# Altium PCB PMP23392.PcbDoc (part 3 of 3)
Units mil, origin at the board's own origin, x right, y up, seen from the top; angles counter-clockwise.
Board outline 5000 x 3400 mil, 6 copper layers (Top Layer, Midlayer 1, Midlayer 2, Midlayer 3, Midlayer 4, Bottom Layer), stack 61.536 mil thick; 247 components, 68 nets, 546 pads, 871 vias.
Unrouted connection lines stored in the file: 21.
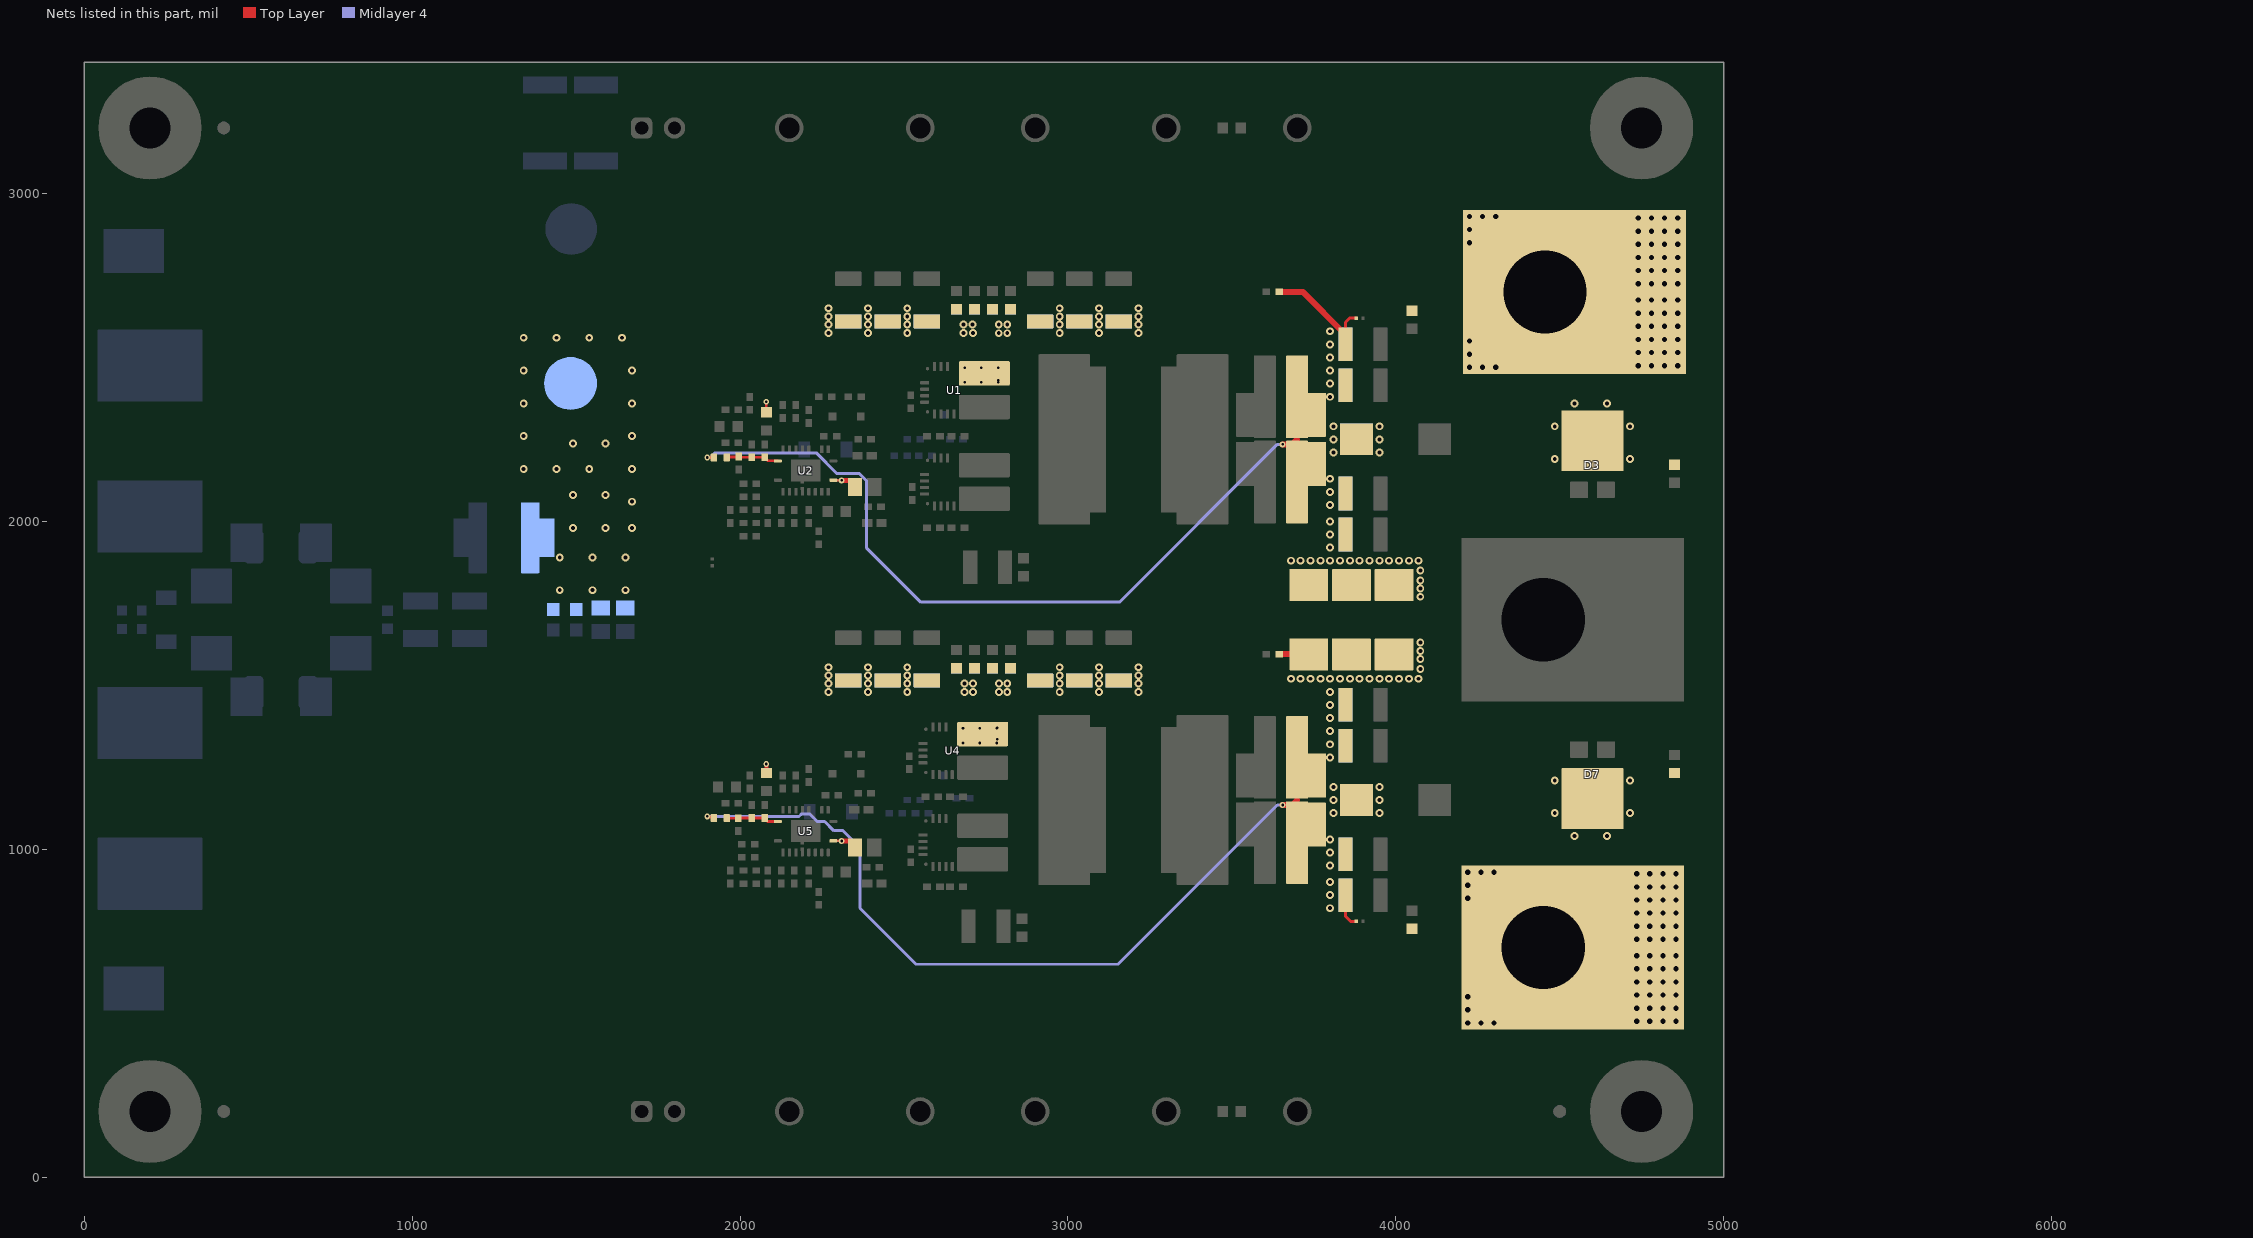
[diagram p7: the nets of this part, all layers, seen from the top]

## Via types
v1: diameter 24, hole 12, Top Layer to Bottom Layer, tented both sides, 526 vias
v2: diameter 32, hole 16, Top Layer to Bottom Layer, 174 vias
v3: diameter 18, hole 8, Top Layer to Bottom Layer, tented both sides, 77 vias
v4: diameter 24, hole 12, Top Layer to Bottom Layer, 46 vias
v5: diameter 19.68, hole 7.87, Top Layer to Bottom Layer, tented both sides, 44 vias
v6: diameter 19.68, hole 7.87, Top Layer to Bottom Layer, tented bottom, 4 vias

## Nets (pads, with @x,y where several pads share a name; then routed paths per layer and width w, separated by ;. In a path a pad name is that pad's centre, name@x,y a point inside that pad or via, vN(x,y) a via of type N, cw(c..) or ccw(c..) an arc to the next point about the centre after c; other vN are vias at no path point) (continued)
VIN: C1.2 C8.1 C9.1 C10.1 C11.1 C12.2 C13.2 C14.2 C15.2 C16.2 C17.1 C18.1 C19.1 C20.1 C21.2 C22.2 C23.2 C24.2 C25.1 C26.1 C27.1 C28.1 C29.2 C30.1 C54.2 C55.2 C56.2 C57.2 C58.2 C59.1 C60.1 C61.1 C62.1 C63.2 C64.2 C65.2 C66.2 C67.2 C68.1 C69.1 C70.1 C71.1 C72.1 C100.2 C101.2 C102.2 C103.2 J1.1 L1.1 R6.2 R29.2 U1.7 U2.10 U4.7 U5.10 | length 214.5
  Top Layer w8: R6.2@2080,2332.56 v3(2080,2365) ; U5.10@2284.65,1025.47 2284.88,1025.24 2309.76,1025.24 v3(2310,1025) ; U2.10@2284.65,2125.47 2284.88,2125.24 2309.76,2125.24 v3(2310,2125)
  Top Layer w12: R29.2@2080,1232.56 v3(2080,1260) ; C72.1@2350.47,1005 C72.1@2350.47,1009.35
  Top Layer w15: v3(2310,1025) 2334.82,1025 C72.1@2350.47,1009.35 ; v3(2310,2125) 2336.32,2125 2350.47,2110.85 C30.1@2350.47,2105
  other v1: 2270,1480 2390,1480 2510,1480 2685,1480 2710,1480 2790,1480 2815,1480 2975,1480 3095,1480 3215,1480 2270,1505 2390,1505 2510,1505 2685,1505 2710,1505 2790,1505 2815,1505 2975,1505 3095,1505 3215,1505 2270,1530 2390,1530 2510,1530 2975,1530 3095,1530 3215,1530 2270,1555 2390,1555 2510,1555 2975,1555 3095,1555 3215,1555 1450,1790 1550,1790 1650,1790 1450,1890 1550,1890 1650,1890 1490,1980 1590,1980 1670,1980 1670,2060 1490,2080 1590,2080 1340,2160 1440,2160 1540,2160 1670,2160 1490,2237.35 1590,2237.35 1340,2260 1670,2260 1340,2360 1670,2360 1340,2460 1670,2460 1340,2560 1440,2560 1540,2560 1640,2560 2789,2574 2815,2574 2270,2575 2390,2575 2510,2575 2681,2575 2710,2575 2975,2575 3095,2575 3215,2575 2270,2600 2390,2600 2510,2600 2681,2600 2709,2600 2789,2600 2815,2600 2975,2600 3095,2600 3215,2600 2270,2625 2390,2625 2510,2625 2975,2625 3095,2625 3215,2625 2270,2650 2390,2650 2510,2650 2975,2650 3095,2650 3215,2650
  other v5: 2680,1324.02 2731.18,1324.02 2782.36,1324.02 2680,1368.9 2731.18,1368.9 2782.36,1368.9 2685,2424.02 2736.18,2424.02 2787.36,2424.02 2685,2468.9 2736.18,2468.9 2787.36,2468.9
  other v6: 2785,1335 2785,1370 2788,2431 2788,2468
VOUT1: C36.1 C37.1 C38.1 C39.1 C40.1 C41.1 C42.1 C43.1 C44.1 C45.1 C46.1 C47.1 D3.3 J9.2 J10.2 J11.2 NT1.2 R5.2 R7.1 R8.2 R13.2 R64.2 R66.2 T1.1 | length 2701.6
  Top Layer w9: v3(1900,2195) R13.2@1920.32,2195 ; C38.1@3846.85,2540 3846.85,2569.53 3846.85,2607.11 3859.74,2620 NT1.2@3880,2620
  Top Layer w18: R7.1@3644.69,2700 3716.38,2700 C38.1@3846.85,2569.53 ; v3(3655,2235) 3684.21,2235 3699.21,2250
  Midlayer 4 w9: v3(1900,2195) 1910.16,2195 1924.15,2208.99 2232.37,2208.99 2294.99,2146.37 2363.78,2146.37 2385.15,2125 2385.15,1919.85 2551.45,1753.55 3157.41,1753.55 3638.86,2235 v3(3655,2235)
  other v1: 4075,1770 4075,1795 4075,1820 4075,1850 3680,1880 3710,1880 3740,1880 3770,1880 3800,1880 3830,1880 3860,1880 3890,1880 3920,1880 3950,1880 3980,1880 4010,1880 4040,1880 4070,1880 3800,1920 3800,1960 3800,2000 3800,2050 3800,2090 3800,2130 4485,2190 4715,2190 3810,2210 3950,2210 3810,2250 3950,2250 3810,2290 3950,2290 4485,2290 4715,2290 4545,2360 4645,2360 3800,2380 3800,2420 3800,2460 3800,2500 3800,2540 3800,2580
  other v2: 4225,2470 4265,2470 4305,2470 4740,2475 4780,2475 4820,2475 4860,2475 4225,2510 4740,2515 4780,2515 4820,2515 4860,2515 4225,2550 4740,2555 4780,2555 4820,2555 4860,2555 4740,2595 4780,2595 4820,2595 4860,2595 4740,2635 4780,2635 4820,2635 4860,2635 4740,2675 4780,2675 4820,2675 4860,2675 4740,2725 4780,2725 4820,2725 4860,2725 4740,2765 4780,2765 4820,2765 4860,2765 4740,2805 4780,2805 4820,2805 4860,2805 4740,2845 4780,2845 4820,2845 4860,2845 4225,2850 4740,2885 4780,2885 4820,2885 4860,2885 4225,2890 4740,2925 4780,2925 4820,2925 4860,2925 4225,2930 4265,2930 4305,2930
VOUT2: C78.1 C79.1 C80.1 C81.1 C82.1 C83.1 C84.1 C85.1 C86.1 C87.1 C88.1 C89.1 D7.3 J9.1 J10.1 J11.1 NT4.2 R30.2 R31.2 R33.2 R38.2 R65.2 R67.2 T3.1 | length 2526.5
  Top Layer w9: v3(1900,1100) 1901.72,1098.28 1917.04,1098.28 R38.2@1920.32,1095 ; J9.1@3734.19,1595 J9.1@3735,1594.19 ; C83.1@3846.85,860 3846.85,795.2 3862.05,780 NT4.2@3880,780
  Top Layer w18: R31.2@3644.69,1595 J9.1@3734.19,1595 ; v3(3655,1135) 3684.21,1135 3699.21,1150
  Midlayer 4 w9: v3(1900,1100) 1920.32,1100 1920.44,1099.88 2179.76,1099.88 2187.85,1107.96 2212.15,1107.96 2234.61,1085.5 2234.61,1084.34 2258.2,1084.34 2285.93,1056.62 2314.04,1056.62 2365.66,1005 2365.66,820.12 2536.81,648.98 3152.84,648.98 3638.86,1135 v3(3655,1135)
  other v1: 3800,820 3800,860 3800,900 3800,950 3800,990 3800,1030 4545,1040 4645,1040 3810,1110 3950,1110 4485,1110 4715,1110 3810,1150 3950,1150 3810,1190 3950,1190 4485,1210 4715,1210 3800,1280 3800,1320 3800,1360 3800,1400 3800,1440 3800,1480 3680,1520 3710,1520 3740,1520 3770,1520 3800,1520 3830,1520 3860,1520 3890,1520 3920,1520 3950,1520 3980,1520 4010,1520 4040,1520 4070,1520 4075,1550 4075,1580 4075,1605 4075,1630
  other v2: 4220,470 4260,470 4300,470 4735,475 4775,475 4815,475 4855,475 4220,510 4735,515 4775,515 4815,515 4855,515 4220,550 4735,555 4775,555 4815,555 4855,555 4735,595 4775,595 4815,595 4855,595 4735,635 4775,635 4815,635 4855,635 4735,675 4775,675 4815,675 4855,675 4735,725 4775,725 4815,725 4855,725 4735,765 4775,765 4815,765 4855,765 4735,805 4775,805 4815,805 4855,805 4735,845 4775,845 4815,845 4855,845 4220,850 4735,885 4775,885 4815,885 4855,885 4220,890 4735,925 4775,925 4815,925 4855,925 4220,930 4260,930 4300,930
VOUTsns1: C49.1 C53.2 R13.1 R16.1 U2.19 | length 158.4
  Top Layer w8: R13.1@1959.68,2195 1961.03,2196.34 1994.66,2196.34 C53.2@1996,2197.69 ; C53.2@1999.84,2195.16 2034.84,2195.16 R16.1@2035,2195.31 C49.1@2074.84,2195.31 ; C49.1@2074.84,2195.16 2074.84,2193.5 2080.84,2187.5 2082.5,2187.5 2085.47,2184.53 U2.19@2115.35,2184.53
VOUTsns2: C91.1 C95.2 R38.1 R41.1 U5.19 | length 156.9
  Top Layer w8: R38.1@1959.68,1095 1959.84,1094.84 1994.84,1094.84 C95.2@1995,1094.69 ; C95.2@1999.84,1095.16 2034.84,1095.16 R41.1@2035,1095.32 C91.1@2075,1095.32 C91.1@2075,1093.35 ; C91.1@2074.84,1093.19 C91.1@2075,1093.35 ; U5.19@2115.35,1084.53 2083.82,1084.53 C91.1@2075,1093.35
pads on no net: FID1.1 FID2.1 FID3.1 FID4.1 FID5.1 FID6.1 H1.1 H2.1 H3.1 H4.1 H5.0 H6.0 H7.0 H8.0 LBL1.0 SH-J1.0 SH-J2.0 U1.1 U1.5 U1.8 U1.9 U1.10 U1.11 U1.12 U1.13 U1.15 U3.1 U3.5 U3.10 U3.11 U3.12 U3.13 U3.15 U4.1 U4.5 U4.8 U4.9 U4.10 U4.11 U4.12 U4.13 U4.15 U6.1 U6.5 U6.10 U6.11 U6.12 U6.13 U6.15

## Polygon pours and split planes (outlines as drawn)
GND on Top Layer "TOP_LAYER_GND" (solid, remove dead copper, pour order 49): 650,1150 650,1530 745,1530 745,1655 900,1655 900,1685 1275,1685 1275,3400 5000,3400 5000,0 1325,0 1325,1150
GNDin on Top Layer "TOP_LAYER_GND_IN" (solid, remove dead copper, pour order 72): 399.45,1149.82 399.45,799.82 299.45,699.82 299.45,474.82 -0.55,474.82 -0.55,1149.82 -0.99,1149.82 -0.99,1684.82 194.01,1684.82 194.01,1655.56 454.01,1655.56 454.01,1530.56 549.01,1530.56 549.01,1149.82
+Vin_Main on Top Layer "TOP_LAYER_+Vin_Main" (solid, remove dead copper, pour order 71): 399.66,2250.58 399.66,2600.58 299.66,2700.58 299.66,2925.58 -0.34,2925.58 -0.34,1715.58 194.66,1715.58 194.66,1745.58 454.66,1745.58 454.66,1870.58 549.66,1870.58 549.66,2250.58
+Filter on Top Layer "TOP_LAYER_+Filter" (solid, remove dead copper, pour order 70): 648.74,1870.69 743.74,1870.69 743.74,1745.69 899.71,1745.69 899.71,1715.19 1234.71,1715.19 1234.71,2100.19 648.74,2100.19
VOUT2 on Top Layer "TOP_LAYER_VOUT2" (solid, remove dead copper, pour order 43): 4200,975 4475,1250 4900,1250 4900,440 3665,440 3665,1645 4090,1645 4090,1507 3885,1507 3885,1260 3915,1230 3945,1230 3975,1200 3975,1100 3945,1070 3915,1070 3885,1040 3885,775 4200,775
VIN on Top Layer "TOP_LAYER_Vin_Phase2" (solid, remove dead copper, pour order 40): 2662.3,1313.27 2662.3,1393.27 2590.56,1465 2255,1465 2255,1570 3230,1570 3230,1465 2894.03,1465 2820,1390.97 2820,1313.27
VOUT1 on Top Layer "TOP_LAYER_VOUT1" (solid, remove dead copper, pour order 38): 4192.8,2423.55 4467.8,2148.55 4900,2148.55 4900,2958.55 3665,2958.55 3665,1753.55 4090,1753.55 4090,1893 3877.8,1893 3877.8,2138.55 3907.8,2168.55 3937.8,2168.55 3967.8,2198.55 3967.8,2298.55 3937.8,2328.55 3907.8,2328.55 3877.8,2358.55 3877.8,2623.55 4192.8,2623.55
VCC2 on Top Layer "TOP_LAYER_VCC1" (solid, remove dead copper, pour order 39): 2225,1000 2235,1000 2235,970 2255,950 2285,950 2285,910 2255,910 2225,940 2225,965
VCC1 on Top Layer "TOP_LAYER_VCC1" (solid, remove dead copper, pour order 34): 2225,2100 2235,2100 2235,2070 2255,2050 2285,2050 2285,2010 2255,2010 2225,2040 2225,2065
AGND2 on Top Layer "TOP_LAYER_AGND2" (solid, remove dead copper, pour order 37): 2215,910 2150,910 2150,875 2015,875 2015,1030 1895,1030 1895,780 2215,780
AGND1 on Top Layer "TOP_LAYER_AGND1" (solid, remove dead copper, pour order 33): 2220,2010 2155,2010 2155,1975 2020,1975 2020,2130 1900,2130 1900,1880 2220,1880
SW2 on Top Layer "TOP_LAYER_SW2" (solid, remove dead copper, pour order 41): 2665,1035 2665,1285 2820,1285 2900,1365 2900,1410 3070,1410 3070,885 2900,885 2900,955 2820,1035
SW1 on Top Layer "TOP_LAYER_SW1" (solid, remove dead copper, pour order 36): 2670,2135 2670,2385 2820,2385 2900,2465 2900,2510 3070,2510 3070,1985 2900,1985 2900,2055 2820,2135
VIN on Top Layer "TOP_LAYER_Vin_Phase1" (solid, remove dead copper, pour order 35): 2665,2415 2665,2495 2600,2560 2255,2560 2255,2665 3230,2665 3230,2560 2890,2560 2825,2495 2825,2415
GND on Midlayer 2 "MIDLAYER_2_GND" (solid, remove dead copper, pour order 60): 650,1150 1325,1150 1325,0.88 4999.05,0.88 4999.05,3400.88 1275,3400.88 1275,1685 900,1685 900,1655 745,1655 745,1530 650,1530
VIN on Midlayer 2 "MIDLAYER_2_VIN" (solid, remove dead copper, pour order 32): 1535,750 1535,1505 1325,1715 1325,2840 3240,2840 3240,750
GNDin on Midlayer 2 "MIDLAYER_2_GND_IN" (solid, remove dead copper, pour order 66): 399.64,1150.3 399.64,800.3 299.64,700.3 299.64,475.3 -0.36,475.3 -0.36,1150.3 -0.8,1150.3 -0.8,1685.3 194.2,1685.3 194.2,1656.04 454.2,1656.04 454.2,1531.04 549.2,1531.04 549.2,1150.3
+Vin_Main on Midlayer 2 "MIDLAYER_2_+Vin_Main" (solid, remove dead copper, pour order 65): 399.72,2250.48 399.72,2600.48 299.72,2700.48 299.72,2925.48 -0.28,2925.48 -0.28,1715.48 194.72,1715.48 194.72,1745.48 454.72,1745.48 454.72,1870.48 549.72,1870.48 549.72,2250.48
+Filter on Midlayer 2 "MIDLAYER_2_+Filter" (solid, remove dead copper, pour order 64): 649.03,1870.5 744.03,1870.5 744.03,1745.5 900,1745.5 900,1715 1235,1715 1235,2100 649.03,2100
VOUT1 on Midlayer 2 "MIDLAYER_2_VOUT1" (solid, remove dead copper, pour order 42): 4192.5,2422.5 4467.5,2147.5 4992.5,2147.5 4992.5,2957.5 3665,2957.5 3665,1752.5 4090,1752.5 4090,1895 3877.5,1895 3877.5,2137.5 3907.5,2167.5 3937.5,2167.5 3967.5,2197.5 3967.5,2297.5 3937.5,2327.5 3907.5,2327.5 3877.5,2357.5 3877.5,2622.5 4192.5,2622.5
VOUT2 on Midlayer 2 "MIDLAYER_2_VOUT2" (solid, remove dead copper, pour order 44): 4200,975 4475,1250 5000,1250 5000,440 3665,440 3665,1645 4090,1645 4090,1505 3885,1505 3885,1260 3915,1230 3945,1230 3975,1200 3975,1100 3945,1070 3915,1070 3885,1040 3885,775 4200,775
GND on Bottom Layer "BOTTOM_LAYER_GND" (solid, remove dead copper, pour order 63): 650,1150 1325,1150 1325,0 5000,0 5000,3400 1275,3400 1275,1685 899.33,1685 899.33,1655.08 745,1655.08 745,1530.08 650,1530.08
+Filter on Bottom Layer "BOTTOM_LAYER_+Filter" (solid, remove dead copper, pour order 47): 648.28,1870.96 743.28,1870.96 743.28,1745.96 899.25,1745.96 899.25,1715 1235,1715 1235,2100.46 648.28,2100.46
VOUT2 on Bottom Layer "BOTTOM_LAYER_VOUT2" (solid, remove dead copper, pour order 57): 4200,975 4475,1250 5000,1250 5000,440 3665,440 3665,1645 4060,1645 4060,1535 3885,1535 3885,1260 3915,1230 3945,1230 3975,1200 3975,1100 3945,1070 3915,1070 3885,1040 3885,775 4200,775
VOUT1 on Bottom Layer "BOTTOM_LAYER_VOUT1" (solid, remove dead copper, pour order 56): 4192.8,2423.55 4467.8,2148.55 4992.8,2148.55 4992.8,2958.55 3665,2958.55 3665,1753.55 4057.8,1753.55 4057.8,1863.55 3877.8,1863.55 3877.8,2138.55 3907.8,2168.55 3937.8,2168.55 3967.8,2198.55 3967.8,2298.55 3937.8,2328.55 3907.8,2328.55 3877.8,2358.55 3877.8,2623.55 4192.8,2623.55
VIN on Bottom Layer "BOTTOM_LAYER_Vin_Phase1" (solid, remove dead copper, pour order 54): 2665,2415 2665,2495 2600,2560 2255,2560 2255,2665 3230,2665 3230,2560 2890,2560 2825,2495 2825,2415
VIN on Bottom Layer "BOTTOM_LAYER_Vin_Phase2" (solid, remove dead copper, pour order 55): 2662.3,1313.27 2662.3,1393.27 2590.56,1465 2255,1465 2255,1570 3230,1570 3230,1465 2894.03,1465 2820,1390.97 2820,1313.27
GNDin on Bottom Layer "BOTTOM_LAYER_GND_IN" (solid, remove dead copper, pour order 48): 400,1150 400,800 300,700 300,475 0,475 0,1150 -0.44,1150 -0.44,1685 194.56,1685 194.56,1655.74 454.56,1655.74 454.56,1530.74 549.56,1530.74 549.56,1150
+Vin_Main on Bottom Layer "BOTTOM_LAYER_+Vin_Main" (solid, remove dead copper, pour order 45): 400,2250 400,2600 300,2700 300,2925 0,2925 0,1715 195,1715 195,1745 455,1745 455,1870 550,1870 550,2250
GND on Midlayer 4 "MIDLAYER_4_GND" (solid, remove dead copper, pour order 50): 650,1150.44 1325,1150.44 1325,0.44 4999.74,0.44 4999.74,3400.44 1275,3400.44 1275,1685 899.07,1685 899.07,1655.52 745,1655.52 745,1530.52 650,1530.52
GNDin on Midlayer 4 "MIDLAYER_4_GND_IN" (solid, remove dead copper, pour order 58): 400,1150 400,800 300,700 300,475 0,475 0,1150 -0.44,1150 -0.44,1685 194.56,1685 194.56,1655.74 454.56,1655.74 454.56,1530.74 549.56,1530.74 549.56,1150
+Filter on Midlayer 4 "MIDLAYER_4_+Filter" (solid, remove dead copper, pour order 62): 648.47,1870.89 743.47,1870.89 743.47,1745.89 899.44,1745.89 899.44,1715 1235,1715 1235,2100.39 648.47,2100.39
+Vin_Main on Midlayer 4 "MIDLAYER_4_+Vin_Main" (solid, remove dead copper, pour order 51): 400,2250 400,2600 300,2700 300,2925 0,2925 0,1715 195,1715 195,1745 455,1745 455,1870 550,1870 550,2250
GND on Midlayer 3 "MIDLAYER_3_GND" (solid, remove dead copper, pour order 59): 650,1150.06 1325,1150.06 1325,0.06 4999.53,0.06 4999.53,3400.06 1275,3400.06 1275,1685 898.86,1685 898.86,1655.15 745,1655.15 745,1530.15 650,1530.15
GNDin on Midlayer 3 "MIDLAYER_3_GND_IN" (solid, remove dead copper, pour order 53): 400,1150 400,800 300,700 300,475 0,475 0,1150 -0.44,1150 -0.44,1685 194.56,1685 194.56,1655.74 454.56,1655.74 454.56,1530.74 549.56,1530.74 549.56,1150
+Filter on Midlayer 3 "MIDLAYER_3_+Filter" (solid, remove dead copper, pour order 46): 649.03,1870.5 744.03,1870.5 744.03,1745.5 900,1745.5 900,1715 1235,1715 1235,2100 649.03,2100
+Vin_Main on Midlayer 3 "MIDLAYER_3_+Vin_Main" (solid, remove dead copper, pour order 52): 400,2250 400,2600 300,2700 300,2925 0,2925 0,1715 195,1715 195,1745 455,1745 455,1870 550,1870 550,2250
GND on Midlayer 1 "MIDLAYER_1_+Filter" (solid, remove dead copper, pour order 61): 650,1150 1325,1150 1325,2.26 5000,2.26 5000,3402.26 1275,3402.26 1275,1685 900,1685 900,1655 745,1655 745,1530 650,1530
GNDin on Midlayer 1 "MIDLAYER_1_GND_IN" (solid, remove dead copper, pour order 69): 399.46,1149.97 399.46,799.97 299.46,699.97 299.46,474.97 -0.54,474.97 -0.54,1149.97 -0.99,1149.97 -0.99,1684.97 194.01,1684.97 194.01,1655.71 454.01,1655.71 454.01,1530.71 549.01,1530.71 549.01,1149.97
+Vin_Main on Midlayer 1 "MIDLAYER_1_+Vin_Main" (solid, remove dead copper, pour order 68): 399.68,2250.58 399.68,2600.58 299.68,2700.58 299.68,2925.58 -0.32,2925.58 -0.32,1715.58 194.68,1715.58 194.68,1745.58 454.68,1745.58 454.68,1870.58 549.68,1870.58 549.68,2250.58
+Filter on Midlayer 1 "MIDLAYER_1_+Filter" (solid, remove dead copper, pour order 67): 648.8,1870.66 743.8,1870.66 743.8,1745.66 899.77,1745.66 899.77,1715.16 1234.77,1715.16 1234.77,2100.16 648.8,2100.16

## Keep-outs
Keep-Out Layer:
  text ".Layer_Name" at 577,-858.49 h60

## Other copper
Top Layer:
  pour cut-out: 2391,1200 2325,1200 2325,1244 2267,1244 2245,1222 2245,1115 2215,1115 2229.84,1129.84 2229.84,1240.84 2262,1273 2391,1273
  pour cut-out: 2259,2332 2317,2332 2317,2280 2391,2280 2391,2360 2269,2360 2250,2341 2226,2341 2226,2226 2215,2215 2245,2215 2245,2271 2259,2285
  pour cut-out: 2255,2663 3230,2663 3230,2687 2255,2687
  pour cut-out: 2255,1568 3230,1568 3230,1592 2255,1592
  pour cut-out: 3635,1420 3665,1420 3665,880 3635,880
  pour cut-out: 3635,2520 3665,2520 3665,1980 3635,1980
  pour cut-out: 2920,1415 2920,1460 3480,1460 3480,1415 3305,1415 3305,885 3480,885 3480,840 2920,840 2920,880 3095,880 3095,1415
  pour cut-out: 2920,2515 2920,2560 3480,2560 3480,2515 3305,2515 3305,1985 3480,1985 3480,1940 2920,1940 2920,1980 3095,1980 3095,2515
  region net NetL4_2: 3635,1990 3330,1990 3330,2510 3635,2510
  region net NetL6_2: 3635,890 3330,890 3330,1410 3635,1410
  text ".Layer_Name" at 577,-858.49 h60
Bottom Layer:
  rectangle net NetC1_1: 1325,2765 1645,3130
  pour cut-out: 1315,1715 1315,1685 1710,1685 1710,1715 1540,1715
  pour cut-out: 2255,1568 3230,1568 3230,1592 2255,1592
  pour cut-out: 2255,2663 3230,2663 3230,2687 2255,2687
  pour cut-out: 1645,3010 1830,3010 1830,2305 1690,2305 1690,2575 1305,2575 1305,2765 1645,2765
  region net VIN: 1325,1715 1325,2575 1690,2575 1690,1715
  text ".Layer_Name" at 577,-858.49 h60

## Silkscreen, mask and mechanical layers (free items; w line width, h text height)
Top Overlay:
  lines w5.91: 2927.28,2525.28 2927.28,2549.21 ; 2932.28,1425.28 2932.28,1449.21 ; 3468,1425 3468,1448.93 ; 3468,2525 3468,2548.93
  lines w6: 1938,1086 1942,1086 ; 1938,1104 1942,1104 ; 1938,2186 1942,2186 ; 1938,2204 1942,2204 ; 1961,913 1961,917 ; 1961,2013 1961,2017 ; 1973,1131 1977,1131 ; 1973,1149 1977,1149 ; 1973,2231 1977,2231 ; 1973,2249 1977,2249 ; 1973,2331 1977,2331 ; 1973,2349 1977,2349 ; 1979,913 1979,917 ; 1979,2013 1979,2017 ; 1986,1073 1986,1077 ; 1987,2176 1987,2180 ; 2004,1073 2004,1077 ; 2005,2176 2005,2180 ; 2021,1203 2021,1207 ; 2021,2358 2021,2362 ; 2023,966 2027,966 ; 2023,984 2027,984 ; 2023,1006 2027,1006 ; 2023,1024 2027,1024 ; 2026,1113 2026,1117 ; 2026,2213 2026,2217 ; 2028,886 2032,886 ; 2028,904 2032,904 ; 2028,926 2032,926 ; 2028,944 2032,944 ; 2028,1946 2032,1946 ; 2028,1964 2032,1964 ; 2028,1986 2032,1986 ; 2028,2004 2032,2004 ; 2028,2026 2032,2026 ; 2028,2044 2032,2044 ; 2028,2066 2032,2066 ; 2028,2084 2032,2084 ; 2028,2106 2032,2106 ; 2028,2124 2032,2124 ; 2039,1203 2039,1207 ; 2039,2358 2039,2362 ; 2044,1113 2044,1117 ; 2044,2213 2044,2217 ; 2066,1113 2066,1117 ; 2066,2213 2066,2217 ; 2076,913 2076,917 ; 2076,2013 2076,2017 ; 2084,1113 2084,1117 ; 2084,2213 2084,2217 ; 2094,913 2094,917 ; 2094,2013 2094,2017 ; 2116,913 2116,917 ; 2116,2013 2116,2017 ; 2121,1203 2121,1207 ; 2121,2333 2121,2337 ; 2134,913 2134,917 ; 2134,2013 2134,2017 ; 2139,1203 2139,1207 ; 2139,2333 2139,2337 ; 2156,913 2156,917 ; 2156,2013 2156,2017 ; 2161,1203 2161,1207 ; 2161,2333 2161,2337 ; 2174,913 2174,917 ; 2174,2013 2174,2017 ; 2179,1203 2179,1207 ; 2179,2333 2179,2337 ; 2201,913 2201,917 ; 2201,1223 2201,1227 ; 2201,2013 2201,2017 ; 2201,2318 2201,2322 ; 2219,913 2219,917 ; 2219,1223 2219,1227 ; 2219,2013 2219,2017 ; 2219,2318 2219,2322 ; 2231,848 2231,852 ; 2231,1948 2231,1952 ; 2249,848 2249,852 ; 2249,1948 2249,1952 ; 2258,2371 2262,2371 ; 2258,2389 2262,2389 ; 2273,2251 2277,2251 ; 2273,2269 2277,2269 ; 2278,1156 2282,1156 ; 2278,1174 2282,1174 ; 2348,1281 2352,1281 ; 2348,1299 2352,1299 ; 2348,2371 2352,2371 ; 2348,2389 2352,2389 ; 2378,1161 2382,1161 ; 2378,1179 2382,1179 ; 2378,2241 2382,2241 ; 2378,2259 2382,2259 ; 2403,936 2407,936 ; 2403,954 2407,954 ; 2408,2036 2412,2036 ; 2408,2054 2412,2054 ; 2506,1263 2506,1267 ; 2511,978 2511,982 ; 2511,2363 2511,2367 ; 2516,2083 2516,2087 ; 2524,1263 2524,1267 ; 2529,978 2529,982 ; 2529,2363 2529,2367 ; 2534,2083 2534,2087 ; 2583,1151 2587,1151 ; 2583,1169 2587,1169 ; 2588,876 2592,876 ; 2588,894 2592,894 ; 2588,1971 2592,1971 ; 2588,1989 2592,1989 ; 2588,2251 2592,2251 ; 2588,2269 2592,2269 ; 2658,876 2662,876 ; 2658,894 2662,894 ; 2658,1151 2662,1151 ; 2658,1169 2662,1169 ; 2663,1971 2667,1971 ; 2663,1989 2667,1989 ; 2663,2251 2667,2251 ; 2663,2269 2667,2269
  text "'.PRJ_Number'.PCB_Rev" at 675,330 h108.27
  text ".Layer_Name" at 577,-858.49 h60
Bottom Overlay:
  circle w20: c400,1485 r10
  lines w6: 1147.91,2020.09 1147.91,2086.02 ; 1412.09,2020.09 1412.09,2086.02
  text ".Layer_Name" at 577,-858.49 h60
Top Paste:
  text ".Layer_Name" at 577,-858.49 h60
Bottom Paste:
  text ".Layer_Name" at 577,-858.49 h60
Top Solder:
  region: 3790,1406 3666,1406 3666,894 3790,894
  rectangle: 3509.9,894 3634,1406
  rectangle: 3510,1994 3634,2506
  region: 3789.91,2506 3666,2506 3666,1994 3789.91,1994
  text ".Layer_Name" at 577,-858.49 h60
  text ".Layer_Name" at 577,-858.49 h60
Bottom Solder:
  text ".Layer_Name" at 577,-858.49 h60
Drill Guide:
  text ".Layer_Name" at 577,-858.49 h60
M1 Board Outline:
  the board outline again, w10
  text ".Layer_Name" at 577,-858.49 h60
M2 Board Dimensions:
  rectangle: 125,-400 500,-275
  rectangle: 0,-275 125,-150
  lines w7: 0,-275 1000,-275 ; 125,-400 125,-150 ; 250,-400 250,-150 ; 500,-400 500,-150 ; 750,-400 750,-150 ; 0,-400 0,-150 1000,-150 1000,-400 0,-400
  text ".Layer_Name" at 577,-858.49 h60
M3 3D STEP Top:
  text ".Layer_Name" at 577,-858.49 h60
M4 3D STEP Bottom:
  text ".Layer_Name" at 577,-858.49 h60
M5 Assembly Top:
  lines w10: -292,-930.17 6308,-930.17 ; -292,-726.83 6310,-726.83 ; -292,-523.5 -292,-1133.5 3713,-1133.5 6310,-1133.5 6310,-523.5 -291.5,-523.5 -291.5,-1133.5 1284,-1133.5 ; 2173,-1133.5 2173,-523.5 ; 3440,-726.83 3440,-523.5 ; 4280,-726.83 4280,-523.5 ; 4902,-1140 4902,-937.17
  text "COMPONENTS MARKED 'DNP' SHOULD NOT BE POPULATED." at 1153.5,-318.5 h60
  text "ASSEMBLY VARIANT:" at 1153,-434 h60
  text ".VariantName" at 2189,-434 h60
  text "PCB VIEWED FROM TOP SIDE" at -228.5,-655.67 h60
  text "BOARD #:" at 2248,-655.67 h60
  text ".PRJ_Number" at 2793.5,-655.67 h60
  text "REV:" at 3638,-655.67 h60
  text ".PCB_Rev" at 3929.5,-655.67 h60
  text "SVN REV:" at 4476,-655.67 h60
  text ".VersionControl_RevNumber" at 4982,-655.67 h60
  text "PLOT NAME =" at -228.5,-1064.34 h60
  text ".plot_File_Name" at 577,-1064.34 h60
  text "GENERATED    :" at 2250,-1064.34 h60
  text ".Print_Date" at 3119.5,-1064.34 h60
  text ".Print_Time" at 3848.5,-1064.34 h60
  text "TEXAS INSTRUMENTS" at 5113,-1064.34 h60
M6 Assembly Bottom:
  lines w10: -292.5,-727.33 6309.5,-727.33 ; -290.5,-930.67 6309.5,-930.67 ; 1115.5,-1140.5 1115.5,-937.67 ; 1737.5,-727.33 1737.5,-524 ; 2577.5,-727.33 2577.5,-524 ; 3844.5,-1134 3844.5,-524 ; 4733.5,-1134 6309,-1134 6309,-524 -292.5,-524 -292.5,-1134 2304.5,-1134 6309.5,-1134 6309.5,-524
  text "COMPONENTS MARKED 'DNP' SHOULD NOT BE POPULATED." at 6102,-318 h60
  text ".VariantName" at 5058,-434 h60
  text "ASSEMBLY VARIANT:" at 6097,-434 h60
  text ".VersionControl_RevNumber" at 1035.5,-656.17 h60
  text "SVN REV:" at 1541.5,-656.17 h60
  text ".PCB_Rev" at 2088,-656.17 h60
  text "REV:" at 2379.5,-656.17 h60
  text ".PRJ_Number" at 3224,-656.17 h60
  text "BOARD #:" at 3769.5,-656.17 h60
  text "PCB VIEWED FROM BOTTOM SIDE" at 6246,-656.17 h60
  text "TEXAS INSTRUMENTS" at 904.5,-1064.84 h60
  text ".Print_Time" at 2169,-1064.84 h60
  text ".Print_Date" at 2898,-1064.84 h60
  text "GENERATED    :" at 3767.5,-1064.84 h60
  text ".plot_File_Name" at 5440.5,-1064.84 h60
  text "PLOT NAME =" at 6246,-1064.84 h60
M9 Title Sheet:
  drawing of 56 lines, arcs and shapes, not listed
  text "1" at 1058.34,13381.39 h70
  text "2" at 4384,13381.39 h70
  text "3" at 7714,13381.39 h70
  text "4" at 11049,13381.39 h70
  text "5" at 14374,13381.39 h70
  text "6" at 17709,13381.39 h70
  text "A" at -463,11603.39 h70
  text "A" at 19237,11603.39 h70
  text "B" at -463,7853.39 h70
  text "B" at 19237,7853.39 h70
  text "C" at -463,4103.39 h70
  text "C" at 19237,4103.39 h70
  text "D" at -463,353.39 h70
  text "D" at 19237,353.39 h70
  text "PROJECT TITLE:" at 16143,268.39 h45
  text ".PRJ_Title" at 16193,135.06 h70
  text "DESIGNED FOR:" at 16143,-32.61 h45
  text ".PRJ_Customer" at 16193,-172.61 h70
  text "FILE NAME:" at 16143,-332.61 h45
  text ".PCB_File_Name_No_Path" at 16193,-452.61 h70
  text "Texas Instruments (TI) and/or its licensors do not warrant the accuracy or completeness of this specification" at 11173.5,-614.45 h45
  text "ENGINEER:" at 16143,-622.61 h45
  text "LAYOUT BY:" at 17648,-622.61 h45
  text "or any information contained therein. TI and/or its licensors do not warrant that this design will meet" at 11128.51,-727.11 h45
  text ".PRJ_Engineer" at 16193,-777.6 h70
  text ".PCB_Layout" at 17698.5,-777.6 h70
  text "the specifications, will be suitable for your application or fit for any particular purpose, or will operate in" at 11128.51,-839.78 h45
  text ".Layer_Name" at 577,-858.49 h60
  text "ALTIUM DESIGNER VERSION:" at 17648,-932.61 h45
  text "an implementation. TI and/or its licensors do not warrant that the design is production worthy. You should" at 11128.51,-952.44 h45
  text "completely validate and test your design implementation to confirm the system functionality for your application." at 11173.5,-1065.11 h45
  text ".print_Scale" at 16193,-1065.94 h70
  text ".Application_BuildNumber" at 17698.5,-1065.94 h70
  text "1" at 1058.34,-1318.61 h70
  text "2" at 4384,-1318.61 h70
  text "3" at 7714,-1318.61 h70
  text "4" at 11049,-1318.61 h70
  text "5" at 14374,-1318.61 h70
  text "6" at 17709,-1318.61 h70
M10 Fab Notes:
  drawing of 189 lines, arcs and shapes, not listed
  text "DESIGN INFORMATION" at 17178.02,6365.17 h60
  text "MIN. TRACK WIDTH:" at 16533.46,6233.05 h60
  text "6" at 17629.7,6233.05 h60
  text "MIL" at 17784.46,6233.05 h60
  text "MIN. CLEARANCE:" at 16533.46,6108.92 h60
  text "MIL" at 17784.46,6108.92 h60
  text "7.874" at 17459.65,6104.33 h60
  text "MIN. VIA PAD SIZE:" at 16533.46,5984.8 h60
  text "18" at 17599.71,5984.8 h60
  text "MIL" at 17784.46,5984.8 h60
  text "0.127mm (5MIL)" at 17228.46,5854.9 h60
  text "MINIMUM ANNULAR RING" at 16204.23,5846.67 h60
  text "EXTERNAL" at 17936.46,5846.67 h60
  text "PER" at 16404.23,5736.55 h60
  text "IPC-D-275 CLASS 2 LEVEL C" at 16624.23,5736.54 h60
  text "MIL, HOLES" at 18112.46,5636.07 h60
  text "+/-" at 17720,5627.48 h60
  text "+/-" at 18574,5627.48 h60
  text "REGISTRATION TOLERANCES:" at 16204.23,5626.42 h60
  text "METAL" at 17404,5626.42 h60
  text "5" at 17980.2,5626.42 h60
  text "3" at 18813.2,5626.42 h60
  text "MIL" at 18929.46,5626.42 h60
  text "HOLE SIZE TOLERANCE (UNLESS OTHERWISE SPECIFIED):" at 16204.23,5528.1 h60
  text "+/-" at 18574,5525.23 h60
  text "3" at 18813.2,5524.17 h60
  text "MIL" at 18929.46,5524.17 h60
  text "MATERIAL:" at 16129.46,5386.52 h60
  text "FR-4 High Tg" at 17115.9,5258 h60
  text "X" at 16971.46,5250.01 h60
  text "FR-4" at 16550.46,5245.49 h60
  text "OTHER" at 18038.46,5245.49 h60
  text "62 MIL (1.6mm) +/-10%" at 16870.56,5102.46 h60
  text "X" at 16750.46,5100.01 h60
  text "THICKNESS:" at 16204.23,5094.24 h60
  text "OTHER" at 18155.46,5094.24 h60
  text "TOLERANCE:" at 16204.23,4955.92 h60
  text "X" at 17052.46,4955.92 h60
  text "ANSI IPC-6012 TYPE 3 CLASS 2" at 17230.48,4955.92 h60
  text "OTHER +/-" at 17230.46,4811.73 h60
  text "BOW & TWIST:" at 16204.23,4666.54 h60
  text "X" at 17052.46,4666.54 h60
  text "ANSI IPC-6012 TYPE 3 CLASS 2" at 17230.48,4666.54 h60
  text "OTHER +/-" at 17230.46,4519.85 h60
  text "DRILLING:" at 16129.46,4389.23 h60
  text "NC_DRILL FILES" at 17890.46,4284.04 h60
  text "REFERENCE:" at 16204.23,4280.1 h60
  text "X" at 16861.46,4280.01 h60
  text "AS SHOWN" at 17039.46,4280.1 h60
  text "X" at 17762.46,4280.1 h60
  text "OTHER" at 18188.46,4137.85 h60
  text "PTH COPPER THICKNESS:" at 16203.91,4134.32 h60
  text "X" at 17343.14,4134.32 h60
  text "20-30 um" at 17471.14,4134.32 h60
  text "BOARD FINISH:" at 16129.46,3986.73 h60
  text "SILKSCREEN:" at 16284.68,3876.6 h60
  text "X" at 17242.46,3876.6 h60
  text "TOP" at 17359.46,3876.6 h60
  text "X" at 17752.46,3876.6 h60
  text "BOTTOM" at 17870.46,3876.6 h60
  text "SILKSCREEN COLOR:" at 16284.68,3721.41 h60
  text "X" at 17241.46,3721.41 h60
  text "WHITE" at 17359.46,3721.41 h60
  text "OTHER" at 17870.46,3721.41 h60
  text "X" at 17372.46,3577.96 h60
  text "GREEN" at 17490.46,3577.96 h60
  text "OTHER" at 18108.46,3577.96 h60
  text "SOLDER RESIST COLOR:" at 16284.68,3571.1 h60
  text "X" at 17372.46,3423.71 h60
  text "MATTE" at 17490.46,3423.71 h60
  text "SEMI-GLOSS" at 18108,3423.07 h60
  text "IMMERSION GOLD (ENIG)" at 17190.46,3250.94 h60
  text "ENEPIG" at 18528,3243.72 h60
  text "SURFACE FINISH:" at 16129.46,3242.72 h60
  text "X" at 17012.46,3242.72 h60
  text "IMM. TIN/SILVER OR EQUIV" at 16459,3105.4 h60
  text "OTHER" at 17890.46,3101.47 h60
  text "ARRAY/PANEL:" at 16129.46,2946.09 h60
  text "X" at 17012.46,2937.87 h60
  text "CUT AND TRIM PER M1 BOARD OUTLINE" at 17190.46,2937.87 h60
  text "N.C. ROUTE" at 17190.46,2801.9 h60
  text "V. SCORE" at 18056.46,2801.9 h60
  text "CERTIFICATION:" at 16129.46,2672.77 h60
  text "MATERIALS AND WORKMANSHIP FOR ALL PCBS" at 16854.46,2672.77 h60
  text "TO MEET OR EXCEED THE REQUIREMENTS OF:" at 16854.46,2578.71 h60
  text "X" at 16491.97,2450.08 h60
  text "ANSI IPC-A-600F CLASS ->" at 16619.96,2450.08 h60
  text "X" at 18267.97,2450.08 h60
  text "2" at 18377.96,2450.08 h60
  text "1" at 18062.96,2448.58 h60
  text "3" at 18731.96,2448.58 h60
  text "X" at 17303.97,2302.39 h60
  text "RoHS" at 17431.96,2302.39 h60
  text "OTHER" at 18076.36,2302.39 h60
  text "PER ORDER" at 18473.42,2302.39 h60
  text "ALL BOARDS MUST MEET OR EXCEED UL94-V0 REQUIREMENTS." at 16157,2148.57 h60
  text "PCB MUST BEAR THE UL94V-0 UL REGISTERED MATERIAL ID NUMBER" at 16157,2032.5 h60
  text "ADDITIONAL REQUIREMENTS:" at 16129.46,1863.08 h60
  text "MICROSECTION:" at 16204.23,1755.95 h60
  text "YES" at 17109.96,1755.95 h60
  text "REQUIRED" at 17971.46,1611.62 h60
  text "BARE BOARD ELEC. TEST:" at 16204.23,1608.76 h60
  text "NONE" at 17509.96,1608.76 h60
  text "X" at 17853.46,1608.76 h60
  text "PER ORDER" at 18563.46,1608.76 h60
  text "XX MIL VIAS REQUIRE NON-CONDUCTIVE FILL AND PLANARIZE" at 16372.38,1403.82 h59
  text "XX MIL VIAS REQUIRE CONDUCTIVE FILL AND PLANARIZE" at 16380.38,1299.84 h60
  text "OUTER XX MIL TRACES REQUIRE 50 OHM SINGLE-ENDED IMPEDANCE" at 16379.39,1136.46 h58
  text "LAYER 2 & 3 (INNER LAYERS) XX MIL WIDE, XX MIL SPACE / TRACES REQUIRE 100 OHM DIFFERENTIAL IMPEDANCE" at 16371.39,900.74 h60
  text ".Layer_Name" at 577,-858.49 h60
M11 Gerber Information:
  lines w10: -292,-930.17 6308,-930.17 ; -292,-726.83 6310,-726.83 ; -292,-523.5 -292,-1133.5 3713,-1133.5 6310,-1133.5 6310,-523.5 -291.5,-523.5 -291.5,-1133.5 1284,-1133.5 ; 2173,-1133.5 2173,-523.5 ; 3440,-726.83 3440,-523.5 ; 4280,-726.83 4280,-523.5 ; 4902,-1140 4902,-937.17
  text "ALL ARTWORK VIEWED FROM TOP SIDE" at -228.5,-655.67 h60
  text "BOARD #:" at 2248,-655.67 h60
  text ".PRJ_Number" at 2793.5,-655.67 h60
  text "REV:" at 3638,-655.67 h60
  text ".PCB_Rev" at 3929.5,-655.67 h60
  text "SVN REV:" at 4476,-655.67 h60
  text ".VersionControl_RevNumber" at 4982,-655.67 h60
  text "LAYER NAME =" at -228.5,-858.49 h60
  text "PLOT NAME =" at -228.5,-1064.34 h60
  text ".plot_File_Name" at 577,-1064.34 h60
  text "GENERATED    :" at 2250,-1064.34 h60
  text ".Print_Date" at 3119.5,-1064.34 h60
  text ".Print_Time" at 3848.5,-1064.34 h60
  text "TEXAS INSTRUMENTS" at 5113,-1064.34 h60
M12 Stackup:
  drawing of 399 lines, arcs and shapes, not listed
  text "Layer" at 14605.06,13091.48 h60
  text "Name" at 15014.97,13091.48 h60
  text "Material" at 15944.72,13091.48 h60
  text "Thickness" at 16804.48,13091.48 h60
  text "Constant" at 17454.32,13091.48 h60
  text "Board Layer Stack" at 18024.18,13091.48 h60
  text "Top Overlay" at 15014.97,12971.48 h60
  text "Top Solder" at 15014.97,12851.48 h60
  text "Solder Resist" at 15944.72,12851.48 h60
  text "0.40mil" at 16804.48,12851.48 h60
  text "3.5" at 17454.32,12851.48 h60
  text "1" at 14605.06,12731.48 h60
  text "Top Layer" at 15014.97,12731.48 h60
  text "CF-005" at 15944.72,12731.48 h60
  text "2.76mil" at 16804.48,12731.48 h60
  text "Dielectric 1" at 15014.97,12611.48 h60
  text "PP-023" at 15944.72,12611.48 h60
  text "9.00mil" at 16804.48,12611.48 h60
  text "4.5" at 17454.32,12611.48 h60
  text "2" at 14605.06,12491.48 h60
  text "Midlayer 1" at 15014.97,12491.48 h60
  text "CF-004" at 15944.72,12491.48 h60
  text "2.76mil" at 16804.48,12491.48 h60
  text "Dielectric 2" at 15014.97,12371.48 h60
  text "PP-023" at 15944.72,12371.48 h60
  text "9.00mil" at 16804.48,12371.48 h60
  text "4.5" at 17454.32,12371.48 h60
  text "3" at 14605.06,12251.48 h60
  text "Midlayer 2" at 15014.97,12251.48 h60
  text "CF-004" at 15944.72,12251.48 h60
  text "2.76mil" at 16804.48,12251.48 h60
  text "Dielectric3" at 15014.97,12131.48 h60
  text "Core-034" at 15944.72,12131.48 h60
  text "9.00mil" at 16804.48,12131.48 h60
  text "4.6" at 17454.32,12131.48 h60
  text "4" at 14605.06,12011.48 h60
  text "Midlayer 3" at 15014.97,12011.48 h60
  text "CF-004" at 15944.72,12011.48 h60
  text "2.76mil" at 16804.48,12011.48 h60
  text "Dielectric 4" at 15014.97,11891.48 h60
  text "PP-023" at 15944.72,11891.48 h60
  text "9.00mil" at 16804.48,11891.48 h60
  text "4.5" at 17454.32,11891.48 h60
  text "5" at 14605.06,11771.48 h60
  text "Midlayer 4" at 15014.97,11771.48 h60
  text "CF-004" at 15944.72,11771.48 h60
  text "2.76mil" at 16804.48,11771.48 h60
  text "Dielectric 5" at 15014.97,11651.48 h60
  text "PP-023" at 15944.72,11651.48 h60
  text "9.00mil" at 16804.48,11651.48 h60
  text "4.5" at 17454.32,11651.48 h60
  text "6" at 14605.06,11531.48 h60
  text "Bottom Layer" at 15014.97,11531.48 h60
  text "CF-005" at 15944.72,11531.48 h60
  text "2.76mil" at 16804.48,11531.48 h60
  text "Bottom Solder" at 15014.97,11411.48 h60
  text "Solder Resist" at 15944.72,11411.48 h60
  text "0.40mil" at 16804.48,11411.48 h60
  text "3.5" at 17454.32,11411.48 h60
  text "Bottom Overlay" at 15014.97,11291.48 h60
  text ".Layer_Name" at 577,-858.49 h60
M13 Component Bodies Top:
  text ".Layer_Name" at 577,-858.49 h60
M14 Component Bodies Bottom:
  text ".Layer_Name" at 577,-858.49 h60
M15 Courtyards Top:
  text ".Layer_Name" at 577,-858.49 h60
M16 Courtyards Bottom:
  text ".Layer_Name" at 577,-858.49 h60
Drill Drawing:
  circle w10: c8443.72,2538.36 r27.63
  lines w10: 8416.09,2400.23 8429.9,2400.23 8429.9,2386.42 8457.53,2386.42 8457.53,2400.23 8471.34,2400.23 8471.34,2427.86 8457.53,2427.86 8457.53,2441.67 8429.9,2441.67 8429.9,2427.86 8416.09,2427.86 8416.09,2400.23 ; 8416.09,2635.06 8443.72,2648.87 8471.34,2635.06 8457.53,2662.68 8471.34,2690.31 8443.72,2676.5 8416.09,2690.31 8429.9,2662.68 8416.09,2635.06 ; 8416.09,2814.63 8471.34,2814.63 8443.72,2759.38 8416.09,2814.63 ; 8416.09,2883.7 8416.09,2897.51 8429.9,2911.32 8416.09,2925.14 8416.09,2938.95 8429.9,2938.95 8443.72,2925.14 8457.53,2938.95 8471.34,2938.95 8471.34,2925.14 8457.53,2911.32 8471.34,2897.51 8471.34,2883.7 8457.53,2883.7 8443.72,2897.51 8429.9,2883.7 8416.09,2883.7 ; 8416.09,3008.02 8471.34,3008.02 8471.34,3063.27 8416.09,3063.27 8416.09,3008.02 ; 8416.09,3159.96 8443.72,3132.34 8471.34,3159.96 8443.72,3187.59 8416.09,3159.96 ; 8416.09,3270.47 8429.9,3270.47 8443.72,3256.66 8457.53,3270.47 8471.34,3270.47 8457.53,3284.28 8471.34,3298.1 8457.53,3298.1 8443.72,3311.91 8429.9,3298.1 8416.09,3298.1 8429.9,3284.28 8416.09,3270.47
  lines w12: 8366,2349.12 11597.49,2349.12 ; 8366,3343.68 11597.49,3343.68 ; 8703.86,2224.8 8703.86,3468 ; 9035.86,2224.8 9035.86,3468 ; 9672.43,2224.8 9672.43,3468 ; 9931.57,2224.8 9931.57,3468 ; 10306.72,2224.8 10306.72,3468 ; 11031.05,2224.8 11031.05,3468 ; 8366,2224.8 11597.49,2224.8 11597.49,3468 8366,3468 8366,2224.8
  text "Symbol" at 8440.59,3380.98 h72
  text "Quantity" at 8741.16,3380.98 h72
  text "Finished Hole Size" at 9073.16,3380.98 h72
  text "Plated" at 9709.72,3380.98 h72
  text "Hole Type" at 9968.86,3380.98 h72
  text "Drill Layer Pair" at 10344.02,3380.98 h72
  text "Hole Tolerance" at 11068.35,3380.98 h72
  text "48" at 8741.16,3256.66 h60
  text "7.87mil (0.200mm)" at 9073.16,3256.66 h60
  text "PTH" at 9709.72,3256.66 h60
  text "Round" at 9968.86,3256.66 h60
  text "Top Layer - Bottom Layer" at 10344.02,3256.66 h60
  text "77" at 8741.16,3132.34 h60
  text "8.00mil (0.203mm)" at 9073.16,3132.34 h60
  text "PTH" at 9709.72,3132.34 h60
  text "Round" at 9968.86,3132.34 h60
  text "Top Layer - Bottom Layer" at 10344.02,3132.34 h60
  text "572" at 8741.16,3008.02 h60
  text "12.00mil (0.305mm)" at 9073.16,3008.02 h60
  text "PTH" at 9709.72,3008.02 h60
  text "Round" at 9968.86,3008.02 h60
  text "Top Layer - Bottom Layer" at 10344.02,3008.02 h60
  text "174" at 8741.16,2883.7 h60
  text "16.00mil (0.406mm)" at 9073.16,2883.7 h60
  text "PTH" at 9709.72,2883.7 h60
  text "Round" at 9968.86,2883.7 h60
  text "Top Layer - Bottom Layer" at 10344.02,2883.7 h60
  text "4" at 8741.16,2759.38 h60
  text "40.00mil (1.016mm)" at 9073.16,2759.38 h60
  text "PTH" at 9709.72,2759.38 h60
  text "Round" at 9968.86,2759.38 h60
  text "Top Layer - Bottom Layer" at 10344.02,2759.38 h60
  text "10" at 8741.16,2635.06 h60
  text "63.00mil (1.600mm)" at 9073.16,2635.06 h60
  text "PTH" at 9709.72,2635.06 h60
  text "Round" at 9968.86,2635.06 h60
  text "Top Layer - Bottom Layer" at 10344.02,2635.06 h60
  text "4" at 8741.16,2510.74 h60
  text "125.98mil (3.200mm)" at 9073.16,2510.74 h60
  text "PTH" at 9709.72,2510.74 h60
  text "Round" at 9968.86,2510.74 h60
  text "Top Layer - Bottom Layer" at 10344.02,2510.74 h60
  text "3" at 8741.16,2386.42 h60
  text "254.00mil (6.452mm)" at 9073.16,2386.42 h60
  text "PTH" at 9709.72,2386.42 h60
  text "Round" at 9968.86,2386.42 h60
  text "Top Layer - Bottom Layer" at 10344.02,2386.42 h60
  text "892 Total" at 8741.16,2262.1 h60
  text ".Layer_Name" at 577,-858.49 h60
M17 Embedded Cavity:
  text ".Layer_Name" at 577,-858.49 h60
M18 Embedded Assembly:
  text ".Layer_Name" at 577,-858.49 h60
M19 Embedded Keepout:
  text ".Layer_Name" at 567,-858.49 h60

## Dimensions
0,-400 to 1000,-400 on M2 Board Dimensions
0,0 to 5000,0 on M2 Board Dimensions
0,0 to 0,3400 on M2 Board Dimensions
